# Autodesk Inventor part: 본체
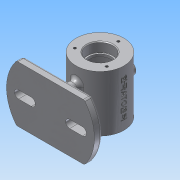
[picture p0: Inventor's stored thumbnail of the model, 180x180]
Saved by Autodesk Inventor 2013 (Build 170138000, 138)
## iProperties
Created: 2017-12
Part Number: 본체
Material: 알루미늄 6061
Document SubType Name: Modeling
Designer: Administrator
Density: 2.71 g/cm^3
Mass: 467.691 g
Surface Area: 486.473 cm^2
Volume: 172.58 cm^3
Author: Administrator
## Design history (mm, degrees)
sketch "스케치1"
  geometry: C1 r 30 at (0, 0); 1 further point
  constraints: 1 centre point, 1 coincident
  dimensions: "d0" = 60 diameter of C1
extrude "돌출1" new body sketch "스케치1" stored distance "d1" = 70; taper "d2" = 0 deg
node "작업 평면1"
sketch "스케치3"
  geometry: L1 (42.426, 35)-(-42.426, 35); L2 (42.426, -35)-(-42.426, -35); L3 (24, 5)-(40, 5); L4 (40, -5)-(24, -5); L5 (-24, 5)-(-40, 5); L6 (-40, -5)-(-24, -5); L7 (5, 15)-(5, -15); L8 (-5, -15)-(-5, 15); A1 r 55 centre (0, 0) between (42.426, -35) and (42.426, 35); A2 r 55 centre (0, 0) between (-42.426, 35) and (-42.426, -35); A3 r 5 centre (40, 0) between (40, -5) and (40, 5); A4 r 5 centre (24, 0) between (24, 5) and (24, -5); A5 r 5 centre (-40, 0) between (-40, 5) and (-40, -5); A6 r 5 centre (-24, 0) between (-24, -5) and (-24, 5); A7 r 5 centre (0, 15) between (5, 15) and (-5, 15); A8 r 5 centre (0, -15) between (-5, -15) and (5, -15); 1 further point
  constraints: 16 end point, 16 point on circle, 12 tangent, 8 centre point, 6 parallel, 2 horizontal alignment, 1 coincident, 1 horizontal, 1 perpendicular, 1 vertical alignment
  dimensions: "d7" = 70 distance between parallel lines of L2 L1; "d8" = 35 distance from line of L1 point (0, 0); "d9" = 55 radius of A1; "d10" = 55 radius of A2; "d11" = 16 distance of L3.start L3.end; "d12" = 16 distance of L5.start L5.end; "d13" = 5 radius of A3; "d14" = 24 distance of point (0, 0) A4.centre; "d15" = 24 distance of point (0, 0) A6.centre; "d16" = 5 radius of A5; "d17" = 30 distance of L7.start L7.end; "d19" = 5 radius of A8; "d20" = 15 distance of A7.centre point (0, 0)
extrude "돌출2" join sketch "스케치3" distance "d21" = 10; taper "d22" = 0 deg
extrude "돌출3" join sketch "스케치3" stored distance "d23" = 10; taper "d24" = 0 deg
fillet "모깎기1" dims "d25" = 5
fillet "모깎기2" dims "d26" = 3
fillet "모깎기3" dims "d27" = 3
node "작업 평면2"
sketch "스케치4"
  geometry: C1 r 8 at (0, 0); 1 further point
  constraints: 1 centre point, 1 coincident
  dimensions: "d29" = 16 diameter of C1
extrude "돌출4" join sketch "스케치4" stored distance "d30" = 10; taper "d31" = 0 deg
sketch "스케치5"
  geometry: L1 (-30, 25)-(-30, 35) reference; L2 (-30, 35)-(30, 35) reference; L3 (30, 35)-(30, 8) reference; L4 (30, 8)-(37, 8) reference; L5 (37, 8)-(37, -8) reference; L6 (37, -8)-(30, -8) reference; L7 (30, -8)-(30, -35) reference; L8 (30, -35)-(-30, -35) reference; L9 (-30, -35)-(-30, -25) reference; L10 (-35, -20)-(-47, -20) reference; L11 (-52, -25)-(-52, -32) reference; L12 (-55, -35)-(-62, -35) reference; L13 (-62, -35)-(-62, 35) reference; L14 (-62, 35)-(-55, 35) reference; L15 (-52, 32)-(-52, 25) reference; L16 (-47, 20)-(-35, 20) reference; L17 (30, 35)-(-30, 35) reference; L18 (0, 35)-(0, -35); L19 (-30, -35)-(30, -35) reference; L20 (0, 35)-(16, 35); L21 (16, 35)-(16, 23.3); L22 (15.7, 23)-(14, 23); L23 (14, 23)-(14, 20); L24 (14, 20)-(22, 20); L25 (25, 17)-(25, -17); L26 (22, -20)-(14, -20); L27 (14, -20)-(14, -23); L28 (14, -23)-(15.7, -23); L29 (16, -23.3)-(16, -35); A1 r 5 centre (-47, -25) between (-47, -20) and (-52, -25) reference; A2 r 3 centre (-55, -32) between (-55, -35) and (-52, -32) reference; A3 r 3 centre (-55, 32) between (-52, 32) and (-55, 35) reference; A4 r 5 centre (-47, 25) between (-52, 25) and (-47, 20) reference; A5 r 3 centre (22, 17) between (25, 17) and (22, 20); A6 r 3 centre (22, -17) between (22, -20) and (25, -17); A7 r 0.3 centre (15.7, -23.3) between (16, -23.3) and (15.7, -23); A8 r 0.3 centre (15.7, 23.3) between (15.7, 23) and (16, 23.3); 4 further points
  constraints: 22 end point, 8 point on circle, 8 point on line, 8 tangent, 6 perpendicular, 4 centre point, 3 parallel, 2 equal radius, 2 midpoint, 1 vertical alignment, 2 other
  dimensions: "d32" = 16 distance of L18.start L20.end; "d33" = 12 distance of L20.end point (16, 23); "d34" = 3 distance of L22.end L23.end; "d35" = 40 distance of point (25, 20) point (25, -20); "d36" = 3 distance of L26.end L27.end; "d37" = 32 diameter of L29 L18; "d38" = 28 diameter of L23 L18; "d39" = 50 diameter of L25 L18; "d40" = 3 radius of A5; "d41" = 0.3 radius of A7
revolve "회전1" sketch "스케치5" stored, may be unused: angle "d42" = 90 deg
hole "구멍1" diameter "d45" = 8; stored, may be unused: countersink angle "d49" = 90 deg, drill point angle "d51" = 118 deg; dims "d43" = 10, "d44" = 10, "d46" = 6, "d47" = 4, "d48" = 2, "d50" = 30
sketch "스케치6"
  geometry: C1 r 16 at (0, 0) reference; 1 further point
  constraints: 1 vertical alignment
  dimensions: "d52" = 23 distance of C1.centre point (0, 23)
hole "구멍2" sketch "스케치6" at (0, 23) diameter "d53" = 3.242; stored, may be unused: countersink angle "d57" = 90 deg, drill point angle "d59" = 118 deg; dims "d54" = 8, "d55" = 4, "d56" = 2, "d58" = 10
node "작업 평면3"
sketch "스케치7"
  geometry: L1 (-30, -35)-(30, -35) reference; 2 further points
  constraints: 1 other
  dimensions: "d63" = 35 distance from line of L1 point (0, 0); "d64" = 30 horizontal distance of point (0, 0) L1.start
feature "엠보싱1" sketch "스케치7" dims "d7" = 70, "d8" = 35, "d9" = 55, "d10" = 55, "d11" = 16, "d12" = 16, "d13" = 5, "d14" = 24, "d15" = 24, "d16" = 5, "d17" = 30, "d19" = 5, "d20" = 15, "d65" = 0.5, "d66" = 0
chamfer "모따기1" distance "d67" = 1; stored, may be unused: second distance "d68" = 2, angle "d69" = 45 deg
fillet "모깎기4" dims "d70" = 3
node "솔리드1"
pattern_circular "원형 패턴1" dims angle "d61" = 360 deg
mirror "대칭1"
node "절단 모서리 투영2"
other parameters: "d3" = -62, "d28" = 37
